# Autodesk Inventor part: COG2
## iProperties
Created: 2010-11
Part Number: COG2
Document SubType Name: Modeling
Designer: ROBERT
Density: 1 g/cm^3
Author: ROBERT
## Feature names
1. Extrusion2
2. Extrusion3
3. TaggingFeature1
